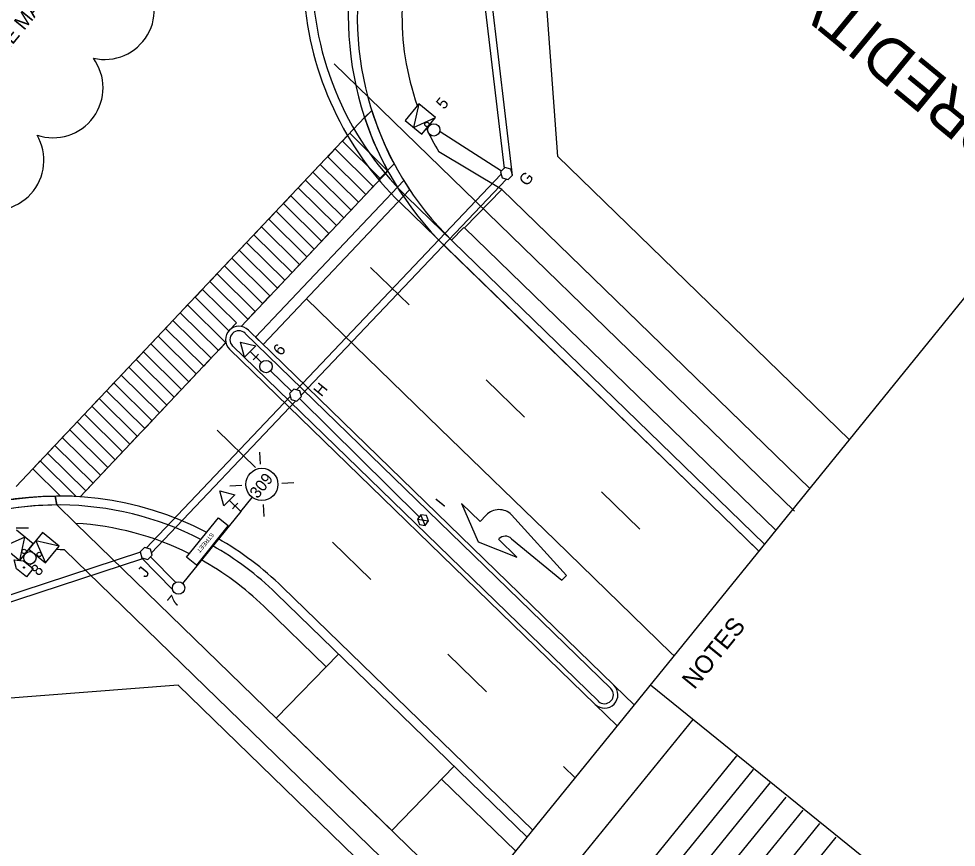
# Model space of a CAD drawing. Extents: x 592613 to 600223, y 4837996 to 4840103.
# Drawn here: x 592778.4 to 592830.8, y 4838979.6 to 4839026 of the extents above; entities that cross this region are included whole.
import ezdxf

# ---------------------------------------------------------------- set-up
doc = ezdxf.new("R2010")
doc.units = 0
for name, color, linetype in [('ENG_BORDER', 7, 'Continuous'), ('ENG_BUS-PAD', 7, 'Continuous'), ('ENG_CURB-BACK', 7, 'Continuous'), ('ENG_CURBSTOP', 7, 'Continuous'), ('ENG_EPAVT', 7, 'Continuous'), ('ENG_KILLSTRIP', 7, 'Continuous'), ('ENG_LIMITS', 7, 'Continuous'), ('ENG_MULTI-TRAIL', 7, 'Continuous'), ('ENG_SH_MULTI-TRAIL', 7, 'Continuous'), ('ENG_SIDEWALK', 7, 'Continuous'), ('ENG_TITLEBLOCK', 7, 'Continuous'), ('ENG_TX_TITLEBLOCK', 7, 'Continuous'), ('Level 12', 7, 'Continuous'), ('Level 31', 7, 'Continuous'), ('Level 32', 7, 'Continuous'), ('Level 9', 7, 'Continuous'), ('PMK_LANE', 7, 'Continuous'), ('PMK_LANE_3-6', 7, 'Continuous'), ('ROW_ENG_ROW', 7, 'Continuous'), ('TCS_100mm-NEW', 7, 'Continuous'), ('TCS_50mm-NEW', 7, 'Continuous'), ('TCS_75mm-NEW', 7, 'Continuous'), ('TCS_ELEC-CHAMBER-NEW', 7, 'Continuous'), ('TCS_LUMINAIRE-NEW', 7, 'Continuous'), ('TCS_POLE-NEW', 7, 'Continuous'), ('TCS_PUSHBUTTON', 7, 'Continuous'), ('TCS_RADAR', 7, 'Continuous'), ('TCS_SIGN', 7, 'Continuous'), ('TCS_SIGNALHEAD', 7, 'Continuous')]:
    doc.layers.add(name, color=color, linetype=linetype)

msp = doc.modelspace()

# ---------------------------------------------------------------- linework, layer by layer
at = {"layer": 'ENG_BORDER'}
for p, q in [((592833.5, 4838972.733), (592813.742, 4838988.708)), ((592773.181, 4838933.919), (592816.128, 4838986.778))]:
    msp.add_line(p, q, dxfattribs=at)
at = {"layer": 'ENG_BUS-PAD'}
for p, q in [((592796.31, 4838990.441), (592792.826, 4838986.855)), ((592799.281, 4838980.583), (592792.826, 4838986.855)), ((592802.765, 4838984.17), (592799.281, 4838980.583))]:
    msp.add_line(p, q, dxfattribs=at)
at = {"layer": 'ENG_CURB-BACK'}
for p, q in [((592820.126, 4838996.582), (592800.129, 4839016.008)), ((592811.531, 4838988.518), (592791.088, 4839008.378)), ((592810.834, 4838987.801), (592790.38, 4839007.672)), ((592806.848, 4838980.204), (592792.819, 4838993.832))]:
    msp.add_line(p, q, dxfattribs=at)
for centre, radius, start, end in [((592814.852, 4839026.104), 17.5, 167.7306, 225.8289), ((592812.324, 4839028.561), 17.5, 178.3407, 225.8289), ((592790.734, 4839008.025), 0.5, 45.2459, 225.2459), ((592780.625, 4838981.28), 17.5, 62.8455, 116.2063), ((592780.625, 4838981.28), 17.5, 45.8289, 60.4988), ((592811.177, 4838988.165), 0.5, 226.4119, 45.2459)]:
    msp.add_arc(centre, radius, start, end, dxfattribs=at)
at = {"layer": 'ENG_CURBSTOP'}
for p, q in [((592798.161, 4839020.844), (592797.765, 4839020.444)), ((592799.42, 4839017.852), (592798.549, 4839016.974)), ((592780.551, 4838998.78), (592780.463, 4838999.279))]:
    msp.add_line(p, q, dxfattribs=at)
for points in [[(592799.42, 4839017.852), (592799.052, 4839017.481), (592798.588, 4839018.391), (592798.266, 4839019.11), (592797.767, 4839020.448), (592798.161, 4839020.844), (592798.507, 4839019.853), (592799.012, 4839018.664), (592799.182, 4839018.286)], [(592780.551, 4838998.78), (592779.535, 4838998.746), (592778.397, 4838998.637), (592777.421, 4838998.484), (592775.714, 4838998.071), (592775.331, 4838998.477), (592777.309, 4838998.972), (592777.839, 4838999.063), (592778.295, 4838999.128), (592778.96, 4838999.203), (592779.671, 4838999.255), (592780.218, 4838999.275), (592780.463, 4838999.279)]]:
    msp.add_lwpolyline(points, close=True, dxfattribs=at)
at = {"layer": 'ENG_EPAVT'}
for p, q in [((592819.81, 4838996.192), (592799.781, 4839015.65)), ((592811.705, 4838988.698), (592791.262, 4839008.558)), ((592810.66, 4838987.622), (592790.206, 4839007.492)), ((592807.164, 4838980.594), (592793.168, 4838994.191))]:
    msp.add_line(p, q, dxfattribs=at)
for centre, radius, start, end in [((592814.852, 4839026.104), 18, 166.783, 225.8289), ((592812.324, 4839028.561), 18, 184.2333, 225.8289), ((592790.734, 4839008.025), 0.75, 45.2459, 225.2459), ((592780.625, 4838981.28), 18, 62.5135, 142.6377), ((592780.625, 4838981.28), 16.5, 63.5712, 86.5779), ((592780.625, 4838981.28), 18, 45.8289, 60.2342), ((592780.625, 4838981.28), 16.5, 45.8289, 61.0962), ((592811.177, 4838988.165), 0.75, 226.4119, 45.2459)]:
    msp.add_arc(centre, radius, start, end, dxfattribs=at)
at = {"layer": 'ENG_KILLSTRIP'}
for p, q in [((592820.758, 4838997.362), (592803.354, 4839014.27)), ((592795.613, 4838989.724), (592792.123, 4838993.115)), ((592806.215, 4838979.424), (592802.069, 4838983.452))]:
    msp.add_line(p, q, dxfattribs=at)
at = {"layer": 'ENG_LIMITS'}
for centre, start, end in [((592783.214, 4839026.487), 257.1728, 42.1728), ((592780.343, 4839022.111), 251.2925, 36.2925), ((592777.034, 4839018.06), 245.2392, 30.2392)]:
    msp.add_arc(centre, 2.793, start, end, dxfattribs=at)
at = {"layer": 'ENG_MULTI-TRAIL'}
for p, q in [((592805.445, 4839016.421), (592803.355, 4839014.27)), ((592822.655, 4838999.702), (592805.445, 4839016.422))]:
    msp.add_line(p, q, dxfattribs=at)
at = {"layer": 'ENG_SH_MULTI-TRAIL'}
for p, q in [((592796.055, 4839023.452), (592821.804, 4838998.438)), ((592802.309, 4839013.194), (592819.713, 4838996.286))]:
    msp.add_line(p, q, dxfattribs=at)
msp.add_lwpolyline([(592822.655, 4838999.702), (592806.713, 4839015.189), (592805.445, 4839016.421), (592803.355, 4839014.27), (592803.354, 4839014.27), (592820.758, 4838997.362)], dxfattribs=at)
at = {"layer": 'ENG_SIDEWALK'}
for p, q in [((592805.445, 4839016.421), (592801.904, 4839018.531)), ((592803.318, 4839014.305), (592802.595, 4839013.576)), ((592781.61, 4838997.751), (592780.551, 4838998.78)), ((592803.686, 4838976.304), (592781.61, 4838997.751)), ((592802.738, 4838975.135), (592780.976, 4838996.276))]:
    msp.add_line(p, q, dxfattribs=at)
for centre, start, end in [((592814.852, 4839026.104), 178.3521, 199.4407), ((592814.852, 4839026.104), 204.683, 210.3244), ((592780.625, 4838981.28), 88.6623, 90.4558)]:
    msp.add_arc(centre, 15, start, end, dxfattribs=at)
at = {"layer": 'ENG_TITLEBLOCK'}
msp.add_line((592770.854, 4838935.809), (592843.567, 4839025.495), dxfattribs=at)
at = {"layer": 'Level 12'}
for p, q in [((592804.22, 4838997.858), (592803.189, 4838998.856)), ((592803.189, 4838998.856), (592804.11, 4838996.715)), ((592804.564, 4838998.214), (592804.22, 4838997.858)), ((592809.055, 4838994.841), (592805.978, 4838998.237)), ((592804.11, 4838996.715), (592806.28, 4838995.863)), ((592806.28, 4838995.863), (592805.25, 4838996.861)), ((592805.977, 4838996.893), (592808.8, 4838994.578)), ((592808.8, 4838994.578), (592809.055, 4838994.841))]:
    msp.add_line(p, q, dxfattribs=at)
for centre, radius, start, end in [((592805.283, 4838997.518), 1, 45.9051, 135.9273), ((592805.629, 4838996.534), 0.5, 45.8987, 135.9224)]:
    msp.add_arc(centre, radius, start, end, dxfattribs=at)
at = {"layer": 'Level 31'}
for p, q in [((592775.654, 4838931.909), (592818.581, 4838984.742)), ((592778.657, 4838933.708), (592819.509, 4838983.988)), ((592777.511, 4838930.4), (592820.437, 4838983.234)), ((592778.439, 4838929.646), (592821.338, 4838982.446)), ((592779.367, 4838928.893), (592822.28, 4838981.709)), ((592780.295, 4838928.139), (592823.222, 4838980.971)), ((592781.222, 4838927.385), (592824.135, 4838980.201))]:
    msp.add_line(p, q, dxfattribs=at)
at = {"layer": 'Level 9'}
msp.add_line((592779.261, 4838995.551), (592779.036, 4838995.432), dxfattribs=at)
at = {"layer": 'PMK_LANE'}
for p, q in [((592778.275, 4838999.816), (592797.765, 4839020.444)), ((592796.934, 4839019.564), (592796.521, 4839019.128)), ((592796.521, 4839019.128), (592798.655, 4839017.018)), ((592799.067, 4839017.454), (592796.934, 4839019.564)), ((592796.109, 4839018.692), (592795.697, 4839018.256)), ((592798.242, 4839016.581), (592796.109, 4839018.692)), ((592795.697, 4839018.256), (592797.83, 4839016.145)), ((592795.285, 4839017.819), (592794.873, 4839017.383)), ((592797.418, 4839015.709), (592795.285, 4839017.819)), ((592790.858, 4839008.765), (592799.067, 4839017.454)), ((592794.873, 4839017.383), (592797.006, 4839015.273)), ((592798.655, 4839017.018), (592799.067, 4839017.454)), ((592791.666, 4839008.165), (592799.949, 4839016.931)), ((592794.461, 4839016.947), (592794.048, 4839016.511)), ((592794.048, 4839016.511), (592796.182, 4839014.4)), ((592796.594, 4839014.836), (592794.461, 4839016.947)), ((592797.83, 4839016.145), (592798.242, 4839016.581)), ((592792.097, 4839007.747), (592800.282, 4839016.41)), ((592793.636, 4839016.074), (592793.224, 4839015.638)), ((592795.769, 4839013.964), (592793.636, 4839016.074)), ((592793.224, 4839015.638), (592795.357, 4839013.528)), ((592797.006, 4839015.273), (592797.418, 4839015.709)), ((592792.812, 4839015.202), (592792.4, 4839014.766)), ((592794.945, 4839013.091), (592792.812, 4839015.202)), ((592792.4, 4839014.766), (592794.533, 4839012.655)), ((592796.182, 4839014.4), (592796.594, 4839014.836)), ((592791.988, 4839014.329), (592791.575, 4839013.893)), ((592791.575, 4839013.893), (592793.709, 4839011.783)), ((592794.121, 4839012.219), (592791.988, 4839014.329)), ((592795.357, 4839013.528), (592795.769, 4839013.964)), ((592791.163, 4839013.457), (592790.751, 4839013.021)), ((592793.296, 4839011.346), (592791.163, 4839013.457)), ((592790.751, 4839013.021), (592792.884, 4839010.91)), ((592794.533, 4839012.655), (592794.945, 4839013.091)), ((592790.339, 4839012.584), (592789.927, 4839012.148)), ((592792.472, 4839010.474), (592790.339, 4839012.584)), ((592789.927, 4839012.148), (592792.06, 4839010.038)), ((592793.709, 4839011.783), (592794.121, 4839012.219)), ((592789.515, 4839011.712), (592789.102, 4839011.276)), ((592789.102, 4839011.276), (592791.236, 4839009.165)), ((592791.648, 4839009.601), (592789.515, 4839011.712)), ((592792.884, 4839010.91), (592793.296, 4839011.346)), ((592788.69, 4839010.839), (592788.278, 4839010.403)), ((592790.59, 4839008.96), (592788.69, 4839010.839)), ((592788.278, 4839010.403), (592790.177, 4839008.524)), ((592792.06, 4839010.038), (592792.472, 4839010.474)), ((592801.977, 4839003.06), (592794.516, 4839010.308)), ((592787.866, 4839009.967), (592787.454, 4839009.531)), ((592789.999, 4839007.856), (592787.866, 4839009.967)), ((592787.454, 4839009.531), (592789.587, 4839007.42)), ((592791.236, 4839009.165), (592791.648, 4839009.601)), ((592787.042, 4839009.094), (592786.629, 4839008.658)), ((592786.629, 4839008.658), (592788.763, 4839006.548)), ((592789.175, 4839006.984), (592787.042, 4839009.094)), ((592790.177, 4839008.524), (592790.59, 4839008.96)), ((592786.217, 4839008.222), (592785.805, 4839007.786)), ((592788.351, 4839006.111), (592786.217, 4839008.222)), ((592781.856, 4838999.238), (592790.002, 4839007.86)), ((592785.805, 4839007.786), (592787.938, 4839005.675)), ((592789.587, 4839007.42), (592789.999, 4839007.856)), ((592785.393, 4839007.349), (592784.981, 4839006.913)), ((592787.526, 4839005.239), (592785.393, 4839007.349)), ((592784.981, 4839006.913), (592787.114, 4839004.803)), ((592788.763, 4839006.548), (592789.175, 4839006.984)), ((592784.569, 4839006.477), (592784.156, 4839006.041)), ((592784.156, 4839006.041), (592786.29, 4839003.93)), ((592786.702, 4839004.366), (592784.569, 4839006.477)), ((592787.938, 4839005.675), (592788.351, 4839006.111)), ((592783.744, 4839005.604), (592783.332, 4839005.168)), ((592785.878, 4839003.494), (592783.744, 4839005.604)), ((592783.332, 4839005.168), (592785.465, 4839003.058)), ((592782.92, 4839004.732), (592782.508, 4839004.296)), ((592785.053, 4839002.621), (592782.92, 4839004.732)), ((592782.508, 4839004.296), (592784.641, 4839002.185)), ((592786.29, 4839003.93), (592786.702, 4839004.366)), ((592782.096, 4839003.859), (592781.684, 4839003.423)), ((592781.684, 4839003.423), (592783.817, 4839001.313)), ((592784.229, 4839001.749), (592782.096, 4839003.859)), ((592785.465, 4839003.058), (592785.878, 4839003.494)), ((592781.271, 4839002.987), (592780.859, 4839002.551)), ((592783.405, 4839000.876), (592781.271, 4839002.987)), ((592808.433, 4838996.789), (592801.977, 4839003.06)), ((592780.859, 4839002.551), (592782.992, 4839000.44)), ((592784.641, 4839002.185), (592785.053, 4839002.621)), ((592780.447, 4839002.114), (592780.035, 4839001.678)), ((592782.58, 4839000.004), (592780.447, 4839002.114)), ((592780.035, 4839001.678), (592782.168, 4838999.568)), ((592783.817, 4839001.313), (592784.229, 4839001.749)), ((592779.623, 4839001.242), (592779.211, 4839000.806)), ((592779.211, 4839000.806), (592780.753, 4838999.28)), ((592781.634, 4838999.252), (592779.623, 4839001.242)), ((592782.992, 4839000.44), (592783.405, 4839000.876)), ((592782.168, 4838999.568), (592782.58, 4839000.004)), ((592814.889, 4838990.517), (592808.433, 4838996.789)), ((592815.068, 4838990.343), (592814.889, 4838990.517)), ((592811.729, 4838988.673), (592812.84, 4838987.595)), ((592810.664, 4838987.618), (592811.893, 4838986.427))]:
    msp.add_line(p, q, dxfattribs=at)
msp.add_lwpolyline([(592799.949, 4839016.931), (592800.282, 4839016.41), (592792.097, 4839007.747), (592791.666, 4839008.165)], close=True, dxfattribs=at)
msp.add_lwpolyline([(592787.114, 4839004.803), (592787.359, 4839005.062), (592787.526, 4839005.239)], dxfattribs=at)
msp.add_arc((592780.625, 4838981.28), 18, 86.7865, 89.5933, dxfattribs=at)
at = {"layer": 'PMK_LANE_3-6'}
for p, q in [((592800.248, 4839009.968), (592798.096, 4839012.058)), ((592806.704, 4839003.696), (592804.552, 4839005.786)), ((592789.511, 4839002.971), (592791.663, 4839000.881)), ((592813.16, 4838997.424), (592811.008, 4838999.515)), ((592795.967, 4838996.7), (592798.119, 4838994.609)), ((592802.423, 4838990.428), (592804.575, 4838988.337)), ((592808.879, 4838984.156), (592809.535, 4838983.519))]:
    msp.add_line(p, q, dxfattribs=at)
at = {"layer": 'ROW_ENG_ROW'}
for p, q in [((592808.565, 4839018.27), (592806.91, 4839040.637)), ((592824.868, 4839002.432), (592808.565, 4839018.27)), ((592787.344, 4838988.695), (592766.831, 4838987.113)), ((592802.105, 4838974.355), (592787.344, 4838988.695))]:
    msp.add_line(p, q, dxfattribs=at)
at = {"layer": 'TCS_100mm-NEW'}
for p, q in [((592806.039, 4839017.197), (592803.96, 4839034.723)), ((592794.208, 4839004.912), (592805.688, 4839017.004)), ((592792.496, 4839006.281), (592793.679, 4839005.138)), ((592785.843, 4838996.102), (592793.917, 4839004.606)), ((592773.628, 4838991.931), (592785.366, 4838995.786)), ((592785.786, 4838995.882), (592787.201, 4838994.443))]:
    msp.add_line(p, q, dxfattribs=at)
at = {"layer": 'TCS_50mm-NEW'}
for p, q in [((592805.589, 4839017.594), (592803.576, 4839034.561)), ((592793.945, 4839005.217), (592805.378, 4839017.259)), ((592785.548, 4838996.372), (592793.599, 4839004.852)), ((592800.813, 4838998.108), (592794.114, 4839004.726)), ((592773.715, 4838992.381), (592785.24, 4838996.166)), ((592785.282, 4838995.824), (592787.025, 4838994.052))]:
    msp.add_line(p, q, dxfattribs=at)
at = {"layer": 'TCS_75mm-NEW'}
msp.add_line((592801.985, 4839019.666), (592805.417, 4839017.466), dxfattribs=at)
at = {"layer": 'TCS_ELEC-CHAMBER-NEW'}
for p, q in [((592805.612, 4839017.65), (592805.368, 4839017.406)), ((592805.946, 4839017.561), (592805.612, 4839017.65)), ((592806.036, 4839017.227), (592805.946, 4839017.561)), ((592805.368, 4839017.406), (592805.457, 4839017.072)), ((592805.457, 4839017.072), (592805.791, 4839016.983)), ((592805.791, 4839016.983), (592806.036, 4839017.227)), ((592793.801, 4839005.26), (592793.557, 4839005.016)), ((592793.557, 4839005.016), (592793.647, 4839004.682)), ((592794.135, 4839005.171), (592793.801, 4839005.26)), ((592794.225, 4839004.837), (592794.135, 4839005.171)), ((592793.647, 4839004.682), (592793.98, 4839004.593)), ((592793.98, 4839004.593), (592794.225, 4839004.837)), ((592800.913, 4838998.232), (592800.713, 4838997.984)), ((592801.142, 4838997.637), (592800.913, 4838998.232)), ((592801.228, 4838998.182), (592800.913, 4838998.232)), ((592801.343, 4838997.885), (592801.228, 4838998.182)), ((592800.713, 4838997.984), (592801.343, 4838997.885)), ((592800.713, 4838997.984), (592800.827, 4838997.686)), ((592800.827, 4838997.686), (592801.142, 4838997.637)), ((592801.142, 4838997.637), (592801.343, 4838997.885)), ((592785.454, 4838996.398), (592785.21, 4838996.153)), ((592785.21, 4838996.153), (592785.299, 4838995.819)), ((592785.788, 4838996.308), (592785.454, 4838996.398)), ((592785.877, 4838995.974), (592785.788, 4838996.308)), ((592785.299, 4838995.819), (592785.633, 4838995.73)), ((592785.633, 4838995.73), (592785.877, 4838995.974))]:
    msp.add_line(p, q, dxfattribs=at)
at = {"layer": 'TCS_LUMINAIRE-NEW'}
for p, q in [((592791.949, 4839001.053), (592791.909, 4839001.728)), ((592790.894, 4838999.863), (592790.22, 4838999.823)), ((592793.139, 4838999.998), (592793.814, 4839000.039)), ((592790.84, 4838998.42), (592791.469, 4838999.197)), ((592792.085, 4838998.809), (592792.125, 4838998.134)), ((592790.84, 4838998.421), (592787.587, 4838994.395)), ((592778.284, 4838997.499), (592778.96, 4838997.492))]:
    msp.add_line(p, q, dxfattribs=at)
msp.add_circle((592792.017, 4838999.931), 0.9, dxfattribs=at)
at = {"layer": 'TCS_POLE-NEW'}
for centre in [(592801.63, 4839019.758), (592792.249, 4839006.522), (592779.048, 4838995.823), (592787.359, 4838994.136)]:
    msp.add_circle(centre, 0.346, dxfattribs=at)
at = {"layer": 'TCS_PUSHBUTTON'}
for centre in [(592801.249, 4839020.064), (592778.72, 4838996.179), (592779.565, 4838996.016)]:
    msp.add_circle(centre, 0.12, dxfattribs=at)
at = {"layer": 'TCS_RADAR'}
msp.add_lwpolyline([(592779.221, 4838995.224), (592778.847, 4838994.763), (592778.304, 4838995.204), (592778.174, 4838995.702), (592778.679, 4838995.664)], close=True, dxfattribs=at)
msp.add_circle((592778.714, 4838995.28), 0.0323, dxfattribs=at)
at = {"layer": 'TCS_SIGN'}
msp.add_lwpolyline([(592790.141, 4838997.622), (592788.353, 4838995.409), (592787.805, 4838995.852), (592789.593, 4838998.064)], close=True, dxfattribs=at)
at = {"layer": 'TCS_SIGNALHEAD'}
for p, q in [((592800.786, 4839021.21), (592800.032, 4839020.276)), ((592800.032, 4839020.276), (592800.965, 4839019.522)), ((592800.965, 4839019.522), (592801.719, 4839020.455)), ((592790.815, 4839007.893), (592791.671, 4839007.675)), ((592791.054, 4839007.044), (592790.815, 4839007.893)), ((592791.671, 4839007.675), (592791.054, 4839007.044)), ((592791.362, 4839007.359), (592791.994, 4839006.743)), ((592791.678, 4839007.051), (592791.524, 4839006.893)), ((592791.678, 4839007.051), (592791.832, 4839007.209)), ((592789.658, 4838999.571), (592790.514, 4838999.353)), ((592789.898, 4838998.722), (592789.658, 4838999.571)), ((592790.514, 4838999.353), (592789.898, 4838998.722)), ((592790.205, 4838999.037), (592790.838, 4838998.421)), ((592790.521, 4838998.729), (592790.368, 4838998.571)), ((592790.521, 4838998.729), (592790.676, 4838998.887)), ((592779.236, 4838996.608), (592778.303, 4838997.363)), ((592779.753, 4838997.24), (592778.995, 4838996.31)), ((592780.683, 4838996.482), (592779.753, 4838997.24)), ((592778.482, 4838995.675), (592779.236, 4838996.608)), ((592778.995, 4838996.31), (592779.925, 4838995.552))]:
    msp.add_line(p, q, dxfattribs=at)
for points in [[(592801.719, 4839020.455), (592800.786, 4839021.21), (592800.498, 4839019.899), (592800.498, 4839019.899)], [(592791.671, 4839007.675), (592791.054, 4839007.044), (592790.815, 4839007.893), (592790.815, 4839007.893)], [(592790.514, 4838999.353), (592789.898, 4838998.722), (592789.658, 4838999.571), (592789.658, 4838999.571)], [(592777.548, 4838996.429), (592778.482, 4838995.675), (592778.769, 4838996.986), (592778.769, 4838996.986)], [(592779.925, 4838995.552), (592780.683, 4838996.482), (592779.374, 4838996.775), (592779.374, 4838996.775)]]:
    msp.add_lwpolyline(points, close=True, dxfattribs=at)

# ---------------------------------------------------------------- texts
at = {"layer": 'ENG_TX_TITLEBLOCK'}
for s, height, rotation, p in [('IS TO BE REPLACED WITH EXISTING SYMBOLOGY ', 0.81055, 50.9012, (592769.012, 4839015.586)), ('ALL DESIGN SYMBOLOGY ON THE MAIN PLAN', 0.81055, 50.9012, (592768.256, 4839016.906)), ('AS SHOWN IN THE MAIN LEGEND.', 0.81055, 50.9012, (592772.376, 4839017.477)), ('NOTES', 1, 50.9062, (592816.203, 4838988.411)), ('NOTES', 1, 50.9062, (592816.203, 4838988.411))]:
    msp.add_text(s, height=height, rotation=rotation, dxfattribs=at).set_placement(p)
at = {"layer": 'Level 32'}
msp.add_text('CREDITVIEW ROAD', height=2.5, rotation=140.5921, dxfattribs=at).set_placement((592834.239, 4839019.43))
at = {"layer": 'TCS_ELEC-CHAMBER-NEW'}
for s, p in [('G', (592806.84, 4839016.565)), ('H', (592795.351, 4839004.79)), ('I', (592802.171, 4838998.612)), ('J', (592785.511, 4838994.665))]:
    msp.add_text(s, height=0.65, rotation=51.0574, dxfattribs=at).set_placement(p)
at = {"layer": 'TCS_LUMINAIRE-NEW'}
msp.add_text('309', height=0.65, rotation=51.283, dxfattribs=at).set_placement((592791.779, 4838999.098))
at = {"layer": 'TCS_POLE-NEW'}
for s, p in [('5', (592802.204, 4839020.861)), ('6', (592793.087, 4839007.078)), ('8', (592779.542, 4838994.76)), ('7', (592787.183, 4838993.016))]:
    msp.add_text(s, height=0.65, rotation=51.0574, dxfattribs=at).set_placement(p)
at = {"layer": 'TCS_SIGN'}
msp.add_text('STREET', height=0.2407, rotation=231.0574, dxfattribs=at).set_placement((592789.182, 4838997.252))

doc.saveas('drawing.dxf')
